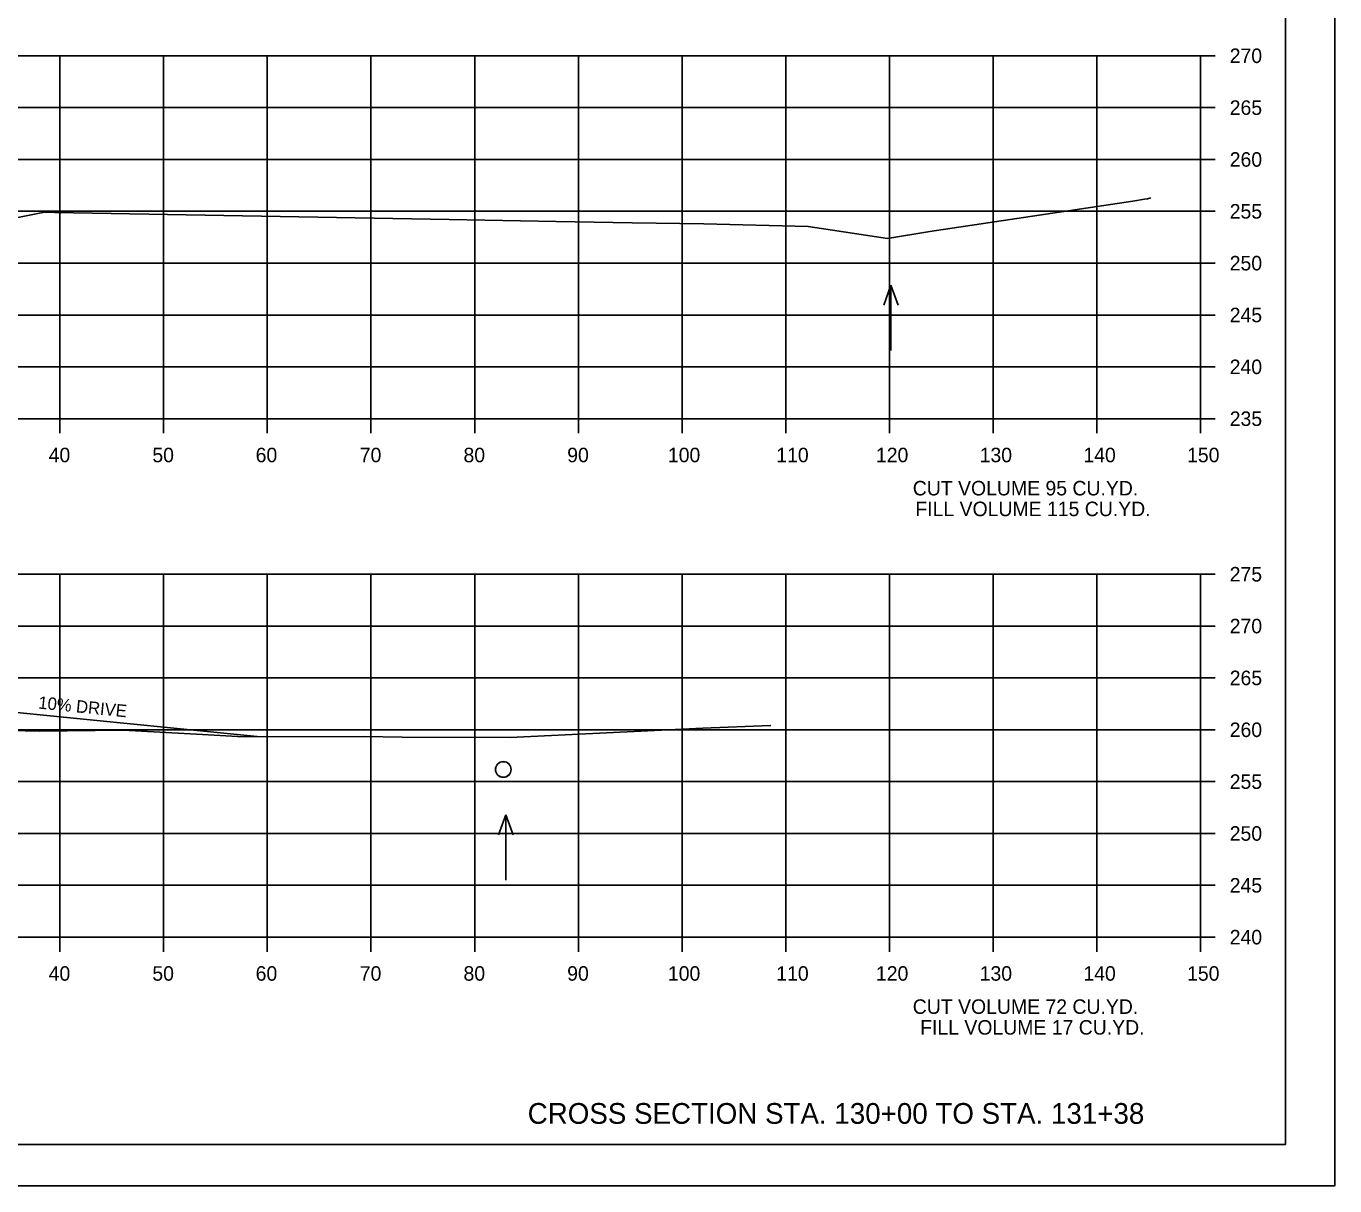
# Model space of a CAD drawing. Extents: x 1103485 to 1107180, y 2010593 to 2011873.
# Drawn here: x 1107053.9 to 1107180.1, y 2011232.8 to 2011344.7 of the extents above; entities that cross this region are included whole.
import ezdxf

# ---------------------------------------------------------------- set-up
doc = ezdxf.new("R2010")
doc.units = 0
for name, color, linetype in [('R_Axis', 7, 'Continuous'), ('R_Axis Annot', 7, 'Continuous'), ('R_Border', 7, 'Continuous'), ('R_Draft', 7, 'Continuous'), ('R_Drive', 7, 'Continuous'), ('R_Exist Surface', 7, 'Continuous'), ('R_Grid', 7, 'Continuous'), ('R_No Plot', 7, 'Continuous'), ('R_Water', 7, 'Continuous'), ('R_Water Annot', 7, 'Continuous')]:
    doc.layers.add(name, color=color, linetype=linetype)

msp = doc.modelspace()

# ---------------------------------------------------------------- linework, layer by layer
at = {"layer": 'R_Axis'}
for p, q in [((1107167.18, 2011306.83), (1107167.18, 2011341.83)), ((1107168.58, 2011341.83), (1107167.18, 2011341.83)), ((1107168.58, 2011336.83), (1107167.18, 2011336.83)), ((1107168.58, 2011331.83), (1107167.18, 2011331.83)), ((1107168.58, 2011326.83), (1107167.18, 2011326.83)), ((1107168.58, 2011321.83), (1107167.18, 2011321.83)), ((1107168.58, 2011316.83), (1107167.18, 2011316.83)), ((1107168.58, 2011311.83), (1107167.18, 2011311.83)), ((1106867.18, 2011306.83), (1107167.18, 2011306.83)), ((1107057.18, 2011305.43), (1107057.18, 2011306.83)), ((1107067.18, 2011305.43), (1107067.18, 2011306.83)), ((1107077.18, 2011305.43), (1107077.18, 2011306.83)), ((1107087.18, 2011305.43), (1107087.18, 2011306.83)), ((1107097.18, 2011305.43), (1107097.18, 2011306.83)), ((1107107.18, 2011305.43), (1107107.18, 2011306.83)), ((1107117.18, 2011305.43), (1107117.18, 2011306.83)), ((1107127.18, 2011305.43), (1107127.18, 2011306.83)), ((1107137.18, 2011305.43), (1107137.18, 2011306.83)), ((1107147.18, 2011305.43), (1107147.18, 2011306.83)), ((1107157.18, 2011305.43), (1107157.18, 2011306.83)), ((1107167.18, 2011305.43), (1107167.18, 2011306.83)), ((1107168.58, 2011306.83), (1107167.18, 2011306.83)), ((1107167.18, 2011256.83), (1107167.18, 2011291.83)), ((1107168.58, 2011291.83), (1107167.18, 2011291.83)), ((1107168.58, 2011286.83), (1107167.18, 2011286.83)), ((1107168.58, 2011281.83), (1107167.18, 2011281.83)), ((1107168.58, 2011276.83), (1107167.18, 2011276.83)), ((1107168.58, 2011271.83), (1107167.18, 2011271.83)), ((1107168.58, 2011266.83), (1107167.18, 2011266.83)), ((1107168.58, 2011261.83), (1107167.18, 2011261.83)), ((1106867.18, 2011256.83), (1107167.18, 2011256.83)), ((1107057.18, 2011255.43), (1107057.18, 2011256.83)), ((1107067.18, 2011255.43), (1107067.18, 2011256.83)), ((1107077.18, 2011255.43), (1107077.18, 2011256.83)), ((1107087.18, 2011255.43), (1107087.18, 2011256.83)), ((1107097.18, 2011255.43), (1107097.18, 2011256.83)), ((1107107.18, 2011255.43), (1107107.18, 2011256.83)), ((1107117.18, 2011255.43), (1107117.18, 2011256.83)), ((1107127.18, 2011255.43), (1107127.18, 2011256.83)), ((1107137.18, 2011255.43), (1107137.18, 2011256.83)), ((1107147.18, 2011255.43), (1107147.18, 2011256.83)), ((1107157.18, 2011255.43), (1107157.18, 2011256.83)), ((1107167.18, 2011255.43), (1107167.18, 2011256.83)), ((1107168.58, 2011256.83), (1107167.18, 2011256.83))]:
    msp.add_line(p, q, dxfattribs=at)
at = {"layer": 'R_Border'}
for q in [(1107175.36, 2011442.29), (1106859.18, 2011236.83)]:
    msp.add_line((1107175.36, 2011236.83), q, dxfattribs=at)
at = {"layer": 'R_Drive'}
msp.add_line((1107048.15, 2011278.97), (1107076.2, 2011276.17), dxfattribs=at)
at = {"layer": 'R_Exist Surface'}
for points in [[(1107045.24, 2011324.65), (1107055.06, 2011326.62), (1107055.7, 2011326.76), (1107056.08, 2011326.74), (1107056.69, 2011326.73), (1107094.71, 2011326.05), (1107105.05, 2011325.85), (1107112.38, 2011325.73), (1107119.29, 2011325.61), (1107129.32, 2011325.36), (1107130.63, 2011325.17), (1107136.97, 2011324.22), (1107141.07, 2011324.87), (1107160.63, 2011327.82), (1107161.76, 2011327.99), (1107162.03, 2011328.03), (1107162.04, 2011328.04), (1107162.38, 2011328.13)], [(1107052.46, 2011276.76), (1107055.19, 2011276.7), (1107063.27, 2011276.79), (1107070.95, 2011276.36), (1107074.32, 2011276.18), (1107075.09, 2011276.16), (1107086.5, 2011276.19), (1107090.19, 2011276.11), (1107100.6, 2011276.09), (1107119.17, 2011276.97), (1107125.7, 2011277.24), (1107125.75, 2011277.23)]]:
    msp.add_lwpolyline(points, dxfattribs=at)
at = {"layer": 'R_Grid'}
for p, q in [((1106867.18, 2011341.83), (1107167.18, 2011341.83)), ((1107057.18, 2011306.83), (1107057.18, 2011341.83)), ((1107067.18, 2011306.83), (1107067.18, 2011341.83)), ((1107077.18, 2011306.83), (1107077.18, 2011341.83)), ((1107087.18, 2011306.83), (1107087.18, 2011341.83)), ((1107097.18, 2011306.83), (1107097.18, 2011341.83)), ((1107107.18, 2011306.83), (1107107.18, 2011341.83)), ((1107117.18, 2011306.83), (1107117.18, 2011341.83)), ((1107127.18, 2011306.83), (1107127.18, 2011341.83)), ((1107137.18, 2011306.83), (1107137.18, 2011341.83)), ((1107147.18, 2011306.83), (1107147.18, 2011341.83)), ((1107157.18, 2011306.83), (1107157.18, 2011341.83)), ((1107167.18, 2011306.83), (1107167.18, 2011341.83)), ((1106867.18, 2011336.83), (1107167.18, 2011336.83)), ((1106867.18, 2011331.83), (1107167.18, 2011331.83)), ((1106867.18, 2011326.83), (1107167.18, 2011326.83)), ((1106867.18, 2011321.83), (1107167.18, 2011321.83)), ((1106867.18, 2011316.83), (1107167.18, 2011316.83)), ((1106867.18, 2011311.83), (1107167.18, 2011311.83)), ((1106867.18, 2011306.83), (1107167.18, 2011306.83)), ((1106867.18, 2011291.83), (1107167.18, 2011291.83)), ((1107057.18, 2011256.83), (1107057.18, 2011291.83)), ((1107067.18, 2011256.83), (1107067.18, 2011291.83)), ((1107077.18, 2011256.83), (1107077.18, 2011291.83)), ((1107087.18, 2011256.83), (1107087.18, 2011291.83)), ((1107097.18, 2011256.83), (1107097.18, 2011291.83)), ((1107107.18, 2011256.83), (1107107.18, 2011291.83)), ((1107117.18, 2011256.83), (1107117.18, 2011291.83)), ((1107127.18, 2011256.83), (1107127.18, 2011291.83)), ((1107137.18, 2011256.83), (1107137.18, 2011291.83)), ((1107147.18, 2011256.83), (1107147.18, 2011291.83)), ((1107157.18, 2011256.83), (1107157.18, 2011291.83)), ((1107167.18, 2011256.83), (1107167.18, 2011291.83)), ((1106867.18, 2011286.83), (1107167.18, 2011286.83)), ((1106867.18, 2011281.83), (1107167.18, 2011281.83)), ((1106867.18, 2011276.83), (1107167.18, 2011276.83)), ((1106867.18, 2011271.83), (1107167.18, 2011271.83)), ((1106867.18, 2011266.83), (1107167.18, 2011266.83)), ((1106867.18, 2011261.83), (1107167.18, 2011261.83)), ((1106867.18, 2011256.83), (1107167.18, 2011256.83))]:
    msp.add_line(p, q, dxfattribs=at)
at = {"layer": 'R_No Plot'}
msp.add_line((1106846.78, 2011232.85), (1107180.12, 2011232.85), dxfattribs=at)
for points in [[(1106846.78, 2011446.19), (1107180.12, 2011446.19), (1107180.12, 2011232.85), (1106846.78, 2011232.85)], [(1107093.1, 2011442.29), (1107093.1, 2011432.41), (1107128.84, 2011432.41), (1107128.84, 2011429.49), (1107152.04, 2011429.49), (1107152.04, 2011405.16), (1107175.36, 2011405.16), (1107175.36, 2011236.83), (1106859.18, 2011236.83), (1106859.18, 2011442.29)]]:
    msp.add_lwpolyline(points, close=True, dxfattribs=at)
at = {"layer": 'R_Water'}
for radius in [0.755, 0.75]:
    msp.add_circle((1107099.94, 2011273), radius, dxfattribs=at)
at = {"layer": 'R_Water Annot'}
for p, q in [((1107137.32, 2011319.7), (1107136.62, 2011317.77)), ((1107137.32, 2011313.41), (1107137.32, 2011319.7)), ((1107137.32, 2011319.7), (1107138.02, 2011317.77)), ((1107100.18, 2011268.63), (1107099.48, 2011266.7)), ((1107100.18, 2011262.34), (1107100.18, 2011268.63)), ((1107100.18, 2011268.63), (1107100.88, 2011266.7))]:
    msp.add_line(p, q, dxfattribs=at)

# ---------------------------------------------------------------- texts
at = {"layer": 'R_Axis Annot'}
for s, p in [('270', (1107169.98, 2011341.13)), ('265', (1107169.98, 2011336.13)), ('260', (1107169.98, 2011331.13)), ('255', (1107169.98, 2011326.13)), ('250', (1107169.98, 2011321.13)), ('245', (1107169.98, 2011316.13)), ('240', (1107169.98, 2011311.13)), ('235', (1107169.98, 2011306.13)), ('40', (1107056.1, 2011302.63)), ('50', (1107066.1, 2011302.63)), ('60', (1107076.06, 2011302.63)), ('70', (1107086.1, 2011302.63)), ('80', (1107096.1, 2011302.63)), ('90', (1107106.1, 2011302.63)), ('100', (1107115.81, 2011302.63)), ('110', (1107126.26, 2011302.63)), ('120', (1107135.87, 2011302.63)), ('130', (1107145.87, 2011302.63)), ('140', (1107155.87, 2011302.63)), ('150', (1107165.87, 2011302.63)), ('CUT VOLUME 95 CU.YD.', (1107139.42, 2011299.43)), ('FILL VOLUME 115 CU.YD.', (1107139.67, 2011297.43)), ('275', (1107169.98, 2011291.13)), ('270', (1107169.98, 2011286.13)), ('265', (1107169.98, 2011281.13)), ('260', (1107169.98, 2011276.13)), ('255', (1107169.98, 2011271.13)), ('250', (1107169.98, 2011266.13)), ('245', (1107169.98, 2011261.13)), ('240', (1107169.98, 2011256.13)), ('40', (1107056.1, 2011252.63)), ('50', (1107066.1, 2011252.63)), ('60', (1107076.06, 2011252.63)), ('70', (1107086.1, 2011252.63)), ('80', (1107096.1, 2011252.63)), ('90', (1107106.1, 2011252.63)), ('100', (1107115.81, 2011252.63)), ('110', (1107126.26, 2011252.63)), ('120', (1107135.87, 2011252.63)), ('130', (1107145.87, 2011252.63)), ('140', (1107155.87, 2011252.63)), ('150', (1107165.87, 2011252.63)), ('CUT VOLUME 72 CU.YD.', (1107139.42, 2011249.43)), ('FILL VOLUME 17 CU.YD.', (1107140.13, 2011247.43))]:
    msp.add_text(s, height=1.4, dxfattribs=at).set_placement(p)
at = {"layer": 'R_Draft'}
msp.add_text('CROSS SECTION STA. 130+00 TO STA. 131+38', height=2, dxfattribs=at).set_placement((1107102.29, 2011238.83))
at = {"layer": 'R_Drive'}
msp.add_text('10% DRIVE', height=1.2, rotation=354.289, dxfattribs=at).set_placement((1107055.06, 2011278.88))

doc.saveas('drawing.dxf')
